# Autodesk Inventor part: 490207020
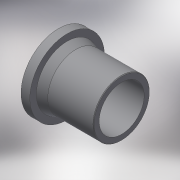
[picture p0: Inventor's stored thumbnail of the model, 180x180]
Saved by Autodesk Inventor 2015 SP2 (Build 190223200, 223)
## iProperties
Created: 2017-07
Part Number: 490207020
Material: Generic
Description: Stub Flange 20
Document SubType Name: Modeling
Designer: Кирилл
Mass: 21.9523 g
Surface Area: 131.123 cm^2
Volume: 21.9523 cm^3
Density: 1 g/cm^3
Appearance: Default
Author: Кирилл
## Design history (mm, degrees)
derived "490207.ipt"
feature "Solid1::490207.ipt"
tag "TaggingFeature1"
body "Solid1"
other parameters: "d0" = 85, "d1" = 26, "d3" = 16, "d4" = 45, "d5" = 7, "d6" = 45, "d17" = 0.4, "d18" = 0.4, "d19" = 0.4, "d21" = 0.4, "d24" = 0.4, "d25" = 0.4, "d26" = 0.2, "d27" = 0, "d32" = 0.2, "L_" = 85, "L_1" = 45, "D_" = 45, "D_1" = 26, "a_" = 7
